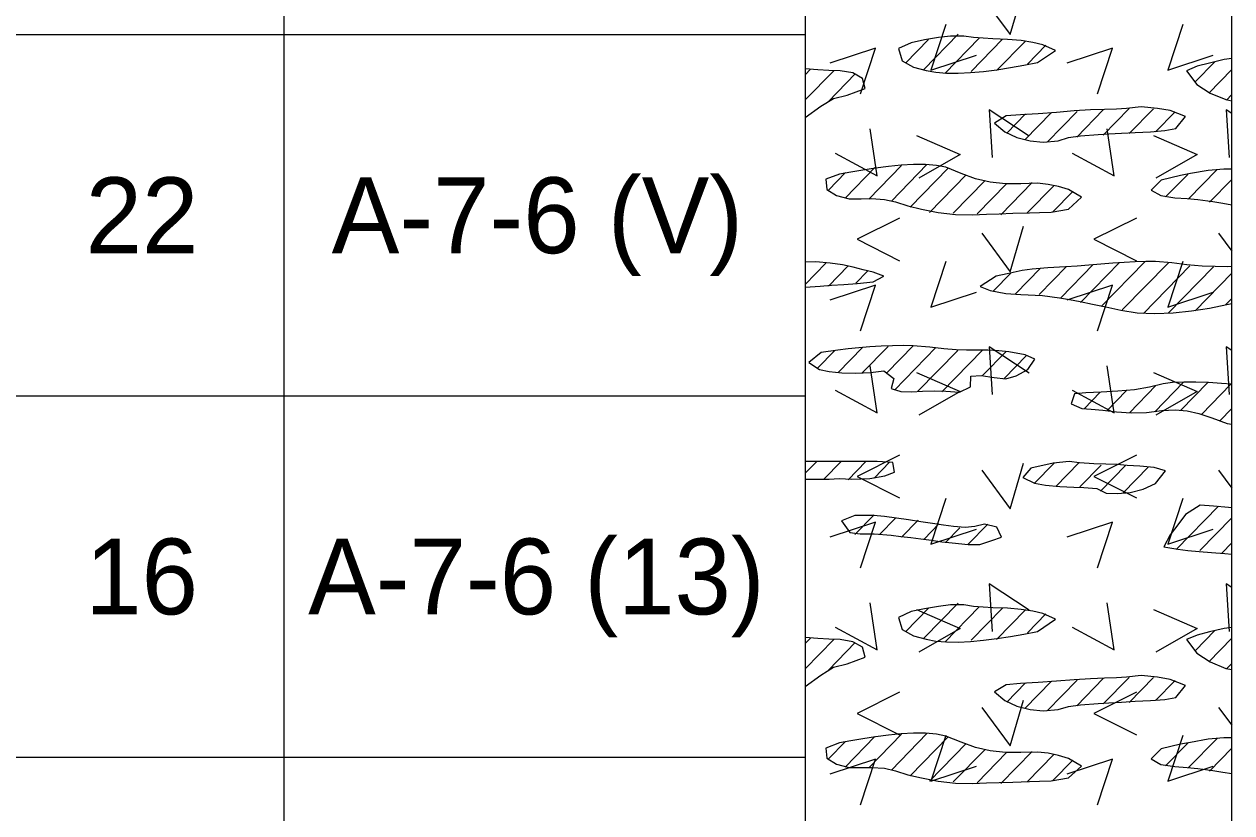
# Model space of a CAD drawing. Extents: x 0 to 0.833, y -0.323 to 0.608.
# Drawn here: x 0.7272 to 0.8333, y 0.2808 to 0.3502 of the extents above; entities that cross this region are included whole.
import ezdxf

# ---------------------------------------------------------------- set-up
doc = ezdxf.new("R2010")
doc.units = 0

msp = doc.modelspace()

# ---------------------------------------------------------------- linework, layer by layer
for points in [[(0, -0.32328), (0.83333, -0.32328), (0.83333, 0.60833), (0, 0.60833)], [(0.81233, 0.34887), (0.81063, 0.34899), (0.80977, 0.34912), (0.8086, 0.34913), (0.80755, 0.34899), (0.80632, 0.34879), (0.80513, 0.34854), (0.80403, 0.34802), (0.80436, 0.34696), (0.80536, 0.34639), (0.80647, 0.3461), (0.8073, 0.34595), (0.80824, 0.34587), (0.80926, 0.34586), (0.81035, 0.34591), (0.81149, 0.34601), (0.81267, 0.34616), (0.81386, 0.34635), (0.81506, 0.34656), (0.81625, 0.34679), (0.81783, 0.34787), (0.81673, 0.34837), (0.81585, 0.34857), (0.8148, 0.34873), (0.81361, 0.34883)], [(0.79583, 0.34196), (0.79719, 0.34295), (0.79831, 0.34365), (0.79951, 0.34392), (0.80111, 0.34453), (0.80086, 0.34541), (0.80002, 0.34589), (0.79889, 0.34608), (0.79791, 0.34611), (0.79694, 0.34617), (0.79583, 0.34625)], [(0.83265, 0.34706), (0.83136, 0.34675), (0.83028, 0.34647), (0.82934, 0.34608), (0.83026, 0.34488), (0.83142, 0.34412), (0.83279, 0.34354), (0.83333, 0.34344), (0.83333, 0.34715)], [(0.82537, 0.34291), (0.82408, 0.34276), (0.82319, 0.3427), (0.82214, 0.34267), (0.82091, 0.34264), (0.81947, 0.34254), (0.81792, 0.34242), (0.81632, 0.3423), (0.81475, 0.34221), (0.81348, 0.34211), (0.81247, 0.34147), (0.81337, 0.34071), (0.81444, 0.34021), (0.81561, 0.33992), (0.81675, 0.33981), (0.81807, 0.33993), (0.81896, 0.3402), (0.82003, 0.34035), (0.82157, 0.34047), (0.82253, 0.34053), (0.82362, 0.34058), (0.82483, 0.34064), (0.82618, 0.34071), (0.82745, 0.34082), (0.82842, 0.34099), (0.82927, 0.34205), (0.82791, 0.34257), (0.82679, 0.34277)], [(0.79885, 0.337), (0.79763, 0.33654), (0.79773, 0.33564), (0.79859, 0.33512), (0.7997, 0.33482), (0.80074, 0.33483), (0.80165, 0.33484), (0.80281, 0.33476), (0.80377, 0.33455), (0.80486, 0.3342), (0.80606, 0.33391), (0.80751, 0.33363), (0.80905, 0.33345), (0.81052, 0.33342), (0.81177, 0.33347), (0.81289, 0.33351), (0.81408, 0.33355), (0.81553, 0.33359), (0.81642, 0.33362), (0.81745, 0.33365), (0.81897, 0.33392), (0.82011, 0.33496), (0.81896, 0.33563), (0.8181, 0.33589), (0.81717, 0.33609), (0.81626, 0.33619), (0.81479, 0.33614), (0.81343, 0.33614), (0.8121, 0.33629), (0.8108, 0.33659), (0.80953, 0.33705), (0.8082, 0.3376), (0.80736, 0.33776), (0.8064, 0.33784), (0.80536, 0.33784), (0.80427, 0.33778), (0.80314, 0.33767), (0.80201, 0.33752), (0.8009, 0.33735), (0.79984, 0.33717)], [(0.83263, 0.33744), (0.83126, 0.33731), (0.82969, 0.33704), (0.82883, 0.33687), (0.82712, 0.33646), (0.82623, 0.33559), (0.82708, 0.3351), (0.82831, 0.33491), (0.82941, 0.33484), (0.83033, 0.33475), (0.83165, 0.33457), (0.83253, 0.33443), (0.83333, 0.33429), (0.83333, 0.33744)], [(0.79583, 0.32704), (0.79715, 0.32715), (0.79814, 0.32722), (0.79922, 0.3273), (0.80039, 0.32739), (0.80179, 0.32751), (0.80275, 0.32802), (0.80179, 0.32836), (0.80091, 0.32858), (0.80003, 0.3288), (0.79909, 0.32901), (0.79803, 0.32917), (0.79677, 0.32927), (0.79583, 0.32925)], [(0.82816, 0.32479), (0.82978, 0.32496), (0.83137, 0.32521), (0.8329, 0.32552), (0.83333, 0.32563), (0.83333, 0.32887), (0.83295, 0.32884), (0.83188, 0.32886), (0.83071, 0.32891), (0.82938, 0.32901), (0.82807, 0.32918), (0.82662, 0.3293), (0.82576, 0.3293), (0.82484, 0.32928), (0.82387, 0.32923), (0.82286, 0.32916), (0.82182, 0.32908), (0.82077, 0.32899), (0.81973, 0.32891), (0.81872, 0.32884), (0.81715, 0.32874), (0.81579, 0.32865), (0.81491, 0.32852), (0.81357, 0.32824), (0.8126, 0.32803), (0.81121, 0.32711), (0.8121, 0.32675), (0.81345, 0.3265), (0.81479, 0.32641), (0.81668, 0.32631), (0.81818, 0.32611), (0.81905, 0.32596), (0.82, 0.32578), (0.82107, 0.32557), (0.82225, 0.32532), (0.82357, 0.32503), (0.82501, 0.3248), (0.82656, 0.32473)], [(0.79708, 0.31981), (0.79794, 0.31963), (0.79904, 0.31952), (0.80028, 0.31949), (0.80156, 0.31954), (0.80274, 0.3197), (0.80361, 0.31903), (0.80338, 0.31814), (0.80422, 0.31787), (0.80517, 0.31785), (0.80613, 0.3179), (0.8072, 0.31793), (0.80818, 0.3179), (0.80939, 0.31783), (0.81037, 0.3183), (0.81038, 0.31924), (0.8113, 0.3193), (0.81244, 0.31912), (0.81346, 0.31901), (0.81438, 0.31927), (0.81539, 0.31981), (0.81601, 0.32072), (0.81517, 0.3211), (0.81374, 0.32137), (0.81285, 0.32146), (0.81187, 0.32152), (0.81, 0.32152), (0.8091, 0.32154), (0.808, 0.32162), (0.80678, 0.32177), (0.8053, 0.3219), (0.80443, 0.32192), (0.80349, 0.3219), (0.80251, 0.32186), (0.80152, 0.3218), (0.80054, 0.32172), (0.79959, 0.32163), (0.7987, 0.32153), (0.79722, 0.32131), (0.79614, 0.32043)], [(0.83241, 0.31859), (0.83129, 0.31866), (0.83017, 0.31869), (0.8291, 0.31869), (0.82811, 0.31866), (0.82728, 0.31857), (0.82608, 0.31827), (0.82476, 0.31804), (0.8233, 0.31791), (0.82183, 0.31782), (0.82051, 0.31776), (0.81951, 0.31767), (0.81922, 0.3168), (0.82013, 0.31638), (0.82097, 0.31633), (0.822, 0.31623), (0.82318, 0.3161), (0.82448, 0.31601), (0.82584, 0.31604), (0.82719, 0.3162), (0.82836, 0.31627), (0.8294, 0.31619), (0.83043, 0.31595), (0.83156, 0.31556), (0.83291, 0.31507), (0.83333, 0.315), (0.83333, 0.31852)], [(0.79583, 0.31018), (0.79676, 0.31017), (0.79792, 0.31019), (0.79882, 0.31023), (0.79992, 0.31018), (0.80151, 0.31023), (0.80282, 0.31048), (0.80367, 0.3108), (0.80354, 0.31164), (0.80216, 0.31173), (0.79583, 0.31173)], [(0.81822, 0.30953), (0.81944, 0.30947), (0.82033, 0.30943), (0.82145, 0.30937), (0.82229, 0.30895), (0.82324, 0.30891), (0.82438, 0.30901), (0.82555, 0.3093), (0.82662, 0.30981), (0.82749, 0.3109), (0.82651, 0.31121), (0.82524, 0.31131), (0.82413, 0.31137), (0.82324, 0.31148), (0.82226, 0.3115), (0.82121, 0.31152), (0.81995, 0.31161), (0.81902, 0.31173), (0.81761, 0.31159), (0.81566, 0.31114), (0.81496, 0.31031), (0.81598, 0.30982), (0.81695, 0.30964)], [(0.83305, 0.30768), (0.83171, 0.30779), (0.83054, 0.30789), (0.82925, 0.30707), (0.82857, 0.30616), (0.82792, 0.30527), (0.82735, 0.30424), (0.82858, 0.30402), (0.82945, 0.30392), (0.83045, 0.30382), (0.83155, 0.30373), (0.83272, 0.30363), (0.83333, 0.30358), (0.83333, 0.30767)], [(0.80066, 0.30538), (0.80188, 0.30537), (0.80339, 0.30524), (0.80423, 0.30515), (0.8051, 0.30504), (0.806, 0.30492), (0.80692, 0.3048), (0.80784, 0.30468), (0.80875, 0.30457), (0.81014, 0.30443), (0.81119, 0.30444), (0.81222, 0.30478), (0.81308, 0.30507), (0.81267, 0.30597), (0.8116, 0.30622), (0.81075, 0.30602), (0.80989, 0.30594), (0.80885, 0.30602), (0.80799, 0.30613), (0.80703, 0.30627), (0.806, 0.30644), (0.80492, 0.3066), (0.80384, 0.30676), (0.8028, 0.30689), (0.80182, 0.30698), (0.8002, 0.30699), (0.79901, 0.30652), (0.79974, 0.30548)], [(0.81233, 0.29887), (0.81063, 0.29899), (0.80977, 0.29912), (0.8086, 0.29913), (0.80755, 0.29899), (0.80632, 0.29879), (0.80513, 0.29854), (0.80403, 0.29802), (0.80436, 0.29696), (0.80536, 0.2964), (0.80647, 0.2961), (0.8073, 0.29595), (0.80824, 0.29587), (0.80926, 0.29586), (0.81035, 0.29591), (0.81149, 0.29601), (0.81267, 0.29616), (0.81386, 0.29635), (0.81506, 0.29656), (0.81625, 0.29679), (0.81783, 0.29787), (0.81673, 0.29837), (0.81585, 0.29857), (0.8148, 0.29873), (0.81361, 0.29883)], [(0.79583, 0.29196), (0.79719, 0.29295), (0.79831, 0.29365), (0.79951, 0.29393), (0.80111, 0.29453), (0.80086, 0.29541), (0.80002, 0.29589), (0.79889, 0.29608), (0.79791, 0.29611), (0.79694, 0.29617), (0.79583, 0.29625)], [(0.83265, 0.29706), (0.83136, 0.29675), (0.83028, 0.29647), (0.82934, 0.29608), (0.83026, 0.29488), (0.83142, 0.29412), (0.83279, 0.29354), (0.83333, 0.29344), (0.83333, 0.29715)], [(0.82537, 0.29291), (0.82408, 0.29276), (0.82319, 0.2927), (0.82214, 0.29267), (0.82091, 0.29264), (0.81947, 0.29254), (0.81792, 0.29242), (0.81632, 0.2923), (0.81475, 0.29221), (0.81348, 0.29211), (0.81247, 0.29147), (0.81337, 0.29071), (0.81444, 0.29021), (0.81561, 0.28992), (0.81675, 0.28981), (0.81807, 0.28993), (0.81896, 0.2902), (0.82003, 0.29035), (0.82157, 0.29047), (0.82253, 0.29053), (0.82362, 0.29058), (0.82483, 0.29065), (0.82618, 0.29071), (0.82745, 0.29082), (0.82842, 0.29099), (0.82927, 0.29205), (0.82791, 0.29257), (0.82679, 0.29277)], [(0.79885, 0.287), (0.79763, 0.28654), (0.79773, 0.28564), (0.79859, 0.28512), (0.7997, 0.28482), (0.80074, 0.28483), (0.80165, 0.28484), (0.80281, 0.28476), (0.80377, 0.28455), (0.80486, 0.2842), (0.80606, 0.28391), (0.80751, 0.28363), (0.80905, 0.28345), (0.81052, 0.28342), (0.81177, 0.28347), (0.81289, 0.28351), (0.81408, 0.28355), (0.81553, 0.28359), (0.81642, 0.28362), (0.81745, 0.28365), (0.81897, 0.28392), (0.82011, 0.28496), (0.81896, 0.28563), (0.8181, 0.28589), (0.81717, 0.28609), (0.81626, 0.28619), (0.81479, 0.28614), (0.81343, 0.28614), (0.8121, 0.28629), (0.8108, 0.28659), (0.80953, 0.28705), (0.8082, 0.2876), (0.80736, 0.28776), (0.8064, 0.28784), (0.80536, 0.28784), (0.80427, 0.28778), (0.80314, 0.28767), (0.80201, 0.28752), (0.8009, 0.28735), (0.79984, 0.28717)], [(0.83263, 0.28744), (0.83126, 0.28731), (0.82969, 0.28704), (0.82883, 0.28687), (0.82712, 0.28646), (0.82623, 0.28559), (0.82708, 0.2851), (0.82831, 0.28491), (0.82941, 0.28484), (0.83033, 0.28475), (0.83165, 0.28457), (0.83253, 0.28443), (0.83333, 0.28429), (0.83333, 0.28744)]]:
    msp.add_lwpolyline(points, close=True)
for points in [[(0.75, 0.55417), (0.75, -0.28575)], [(0.75, 0.55417), (0.75, -0.28575)], [(0.79583, 0.55417), (0.79583, -0.28575)], [(0.83333, -0.28575), (0.83333, 0.50165)], [(0.81134, 0.35262), (0.81384, 0.34925), (0.81503, 0.35325)], [(0.80818, 0.35013), (0.80687, 0.34613), (0.81087, 0.34744)], [(0.82901, 0.35013), (0.8277, 0.34613), (0.8317, 0.34744)], [(0.725, 0.34925), (0.75, 0.34925)], [(0.75, 0.34925), (0.79583, 0.34925)], [(0.80465, 0.34675), (0.80667, 0.34883)], [(0.80626, 0.34619), (0.80928, 0.34928)], [(0.80809, 0.34585), (0.81111, 0.34895)], [(0.81041, 0.34602), (0.81318, 0.34885)], [(0.81264, 0.34609), (0.81518, 0.34869)], [(0.81536, 0.34667), (0.81699, 0.34833)], [(0.80069, 0.34405), (0.802, 0.34805), (0.798, 0.34674)], [(0.82152, 0.34405), (0.82284, 0.34805), (0.81884, 0.34674)], [(0.7963, 0.34621), (0.79583, 0.34572)], [(0.8301, 0.34509), (0.83184, 0.34687)], [(0.83131, 0.34412), (0.83333, 0.34619)], [(0.79834, 0.34608), (0.79583, 0.34351)], [(0.79786, 0.34338), (0.80023, 0.34581)], [(0.83285, 0.34349), (0.83333, 0.34398)], [(0.81551, 0.34033), (0.81201, 0.34264), (0.81226, 0.33845)], [(0.81519, 0.34228), (0.81354, 0.34058)], [(0.81514, 0.34001), (0.81748, 0.34241)], [(0.81709, 0.3398), (0.81974, 0.34251)], [(0.8197, 0.34025), (0.82203, 0.34265)], [(0.82202, 0.34042), (0.8243, 0.34275)], [(0.82431, 0.34055), (0.82644, 0.34274)], [(0.82663, 0.34071), (0.82834, 0.34247)], [(0.83333, 0.34232), (0.83284, 0.34264), (0.83309, 0.33845)], [(0.79847, 0.33884), (0.80215, 0.33684), (0.80153, 0.34097)], [(0.8193, 0.33884), (0.82299, 0.33684), (0.82236, 0.34097)], [(0.80562, 0.34039), (0.80946, 0.33871), (0.80581, 0.33664)], [(0.82645, 0.34039), (0.83029, 0.33871), (0.82664, 0.33664)], [(0.80142, 0.3348), (0.8043, 0.33775)], [(0.80653, 0.33783), (0.8034, 0.33461)], [(0.79938, 0.33713), (0.79786, 0.33558)], [(0.79933, 0.33487), (0.80195, 0.33756)], [(0.80506, 0.3341), (0.8084, 0.33752)], [(0.80997, 0.33693), (0.80675, 0.33362)], [(0.82751, 0.33498), (0.82945, 0.33696)], [(0.83203, 0.33739), (0.82949, 0.33479)], [(0.81164, 0.33642), (0.80884, 0.33356)], [(0.81353, 0.33614), (0.81094, 0.33349)], [(0.81303, 0.33342), (0.81579, 0.33625)], [(0.81534, 0.33358), (0.81768, 0.33597)], [(0.83138, 0.33452), (0.83333, 0.33652)], [(0.8176, 0.33368), (0.81934, 0.33547)], [(0.83333, 0.3343), (0.83333, 0.33431)], [(0.80412, 0.33313), (0.80038, 0.33126), (0.80412, 0.32938)], [(0.81134, 0.33179), (0.81384, 0.32841), (0.81503, 0.33241)], [(0.82496, 0.33313), (0.82121, 0.33126), (0.82496, 0.32938)], [(0.83217, 0.33179), (0.83333, 0.33023)], [(0.79765, 0.32915), (0.79583, 0.32728)], [(0.80818, 0.3293), (0.80687, 0.3253), (0.81087, 0.32661)], [(0.82004, 0.32571), (0.82346, 0.32922)], [(0.82569, 0.32929), (0.82184, 0.32535)], [(0.82775, 0.32919), (0.8237, 0.32505)], [(0.82901, 0.3293), (0.8277, 0.3253), (0.8317, 0.32661)], [(0.7996, 0.32894), (0.79786, 0.32715)], [(0.8013, 0.32846), (0.80027, 0.32741)], [(0.81392, 0.3283), (0.81235, 0.32669)], [(0.8143, 0.32648), (0.8165, 0.32873)], [(0.8164, 0.32641), (0.81879, 0.32886)], [(0.81829, 0.32613), (0.82114, 0.32905)], [(0.82964, 0.32892), (0.82557, 0.32474)], [(0.83173, 0.32885), (0.82774, 0.32476)], [(0.83333, 0.32827), (0.83012, 0.32498)], [(0.80069, 0.32322), (0.802, 0.32722), (0.798, 0.32591)], [(0.82152, 0.32322), (0.82284, 0.32722), (0.81884, 0.32591)], [(0.83281, 0.32552), (0.83333, 0.32606)], [(0.79871, 0.31955), (0.80085, 0.32174)], [(0.80083, 0.31951), (0.80311, 0.32185)], [(0.80534, 0.32192), (0.80299, 0.31951)], [(0.80367, 0.318), (0.80732, 0.32174)], [(0.81551, 0.31949), (0.81201, 0.32181), (0.81226, 0.31762)], [(0.83333, 0.32148), (0.83284, 0.32181), (0.83309, 0.31762)], [(0.79844, 0.32149), (0.79691, 0.31992)], [(0.80571, 0.31788), (0.80924, 0.32149)], [(0.81142, 0.32151), (0.80785, 0.31786)], [(0.81141, 0.31929), (0.81348, 0.32141)], [(0.81528, 0.32104), (0.81331, 0.31903)], [(0.79847, 0.31801), (0.80215, 0.31601), (0.80153, 0.32014)], [(0.8193, 0.31801), (0.82299, 0.31601), (0.82236, 0.32014)], [(0.80562, 0.31956), (0.80946, 0.31787), (0.80581, 0.31581)], [(0.82645, 0.31956), (0.83029, 0.31787), (0.82664, 0.31581)], [(0.82909, 0.31869), (0.82656, 0.3161)], [(0.82885, 0.31623), (0.83122, 0.31866)], [(0.83325, 0.31852), (0.83065, 0.31586)], [(0.725, 0.3175), (0.75, 0.3175)], [(0.75, 0.3175), (0.79583, 0.3175)], [(0.82035, 0.31637), (0.82176, 0.31782)], [(0.82233, 0.31619), (0.82408, 0.31798)], [(0.82433, 0.31602), (0.82666, 0.31841)], [(0.83333, 0.3164), (0.83227, 0.31531)], [(0.80412, 0.3123), (0.80038, 0.31042), (0.80412, 0.30855)], [(0.82496, 0.3123), (0.82121, 0.31042), (0.82496, 0.30855)], [(0.79583, 0.3107), (0.79681, 0.3117)], [(0.79898, 0.31172), (0.79747, 0.31017)], [(0.80116, 0.31173), (0.79959, 0.31013)], [(0.80328, 0.31169), (0.80188, 0.31026)], [(0.81134, 0.31096), (0.81384, 0.30758), (0.81503, 0.31158)], [(0.8177, 0.31159), (0.81596, 0.30981)], [(0.81988, 0.31161), (0.81785, 0.30953)], [(0.82185, 0.31142), (0.81997, 0.30949)], [(0.824, 0.31141), (0.82178, 0.30913)], [(0.82601, 0.31125), (0.82378, 0.30897)], [(0.83217, 0.31096), (0.83333, 0.30939)], [(0.80818, 0.30847), (0.80687, 0.30447), (0.81087, 0.30578)], [(0.82901, 0.30847), (0.8277, 0.30447), (0.8317, 0.30578)], [(0.80188, 0.30703), (0.8002, 0.30531)], [(0.83217, 0.30781), (0.82844, 0.30399)], [(0.80069, 0.30239), (0.802, 0.30639), (0.798, 0.30507)], [(0.8038, 0.30679), (0.80237, 0.30532)], [(0.80575, 0.30657), (0.80429, 0.30508)], [(0.80758, 0.30624), (0.80627, 0.30489)], [(0.80941, 0.3059), (0.80816, 0.30462)], [(0.81188, 0.30621), (0.81016, 0.30446)], [(0.82152, 0.30239), (0.82284, 0.30639), (0.81884, 0.30507)], [(0.83333, 0.30679), (0.83052, 0.30391)], [(0.83333, 0.30457), (0.83245, 0.30367)], [(0.81551, 0.29866), (0.81201, 0.30097), (0.81226, 0.29678)], [(0.83333, 0.30065), (0.83284, 0.30097), (0.83309, 0.29678)], [(0.79847, 0.29718), (0.80215, 0.29518), (0.80153, 0.2993)], [(0.80465, 0.29675), (0.80667, 0.29883)], [(0.80562, 0.29872), (0.80946, 0.29704), (0.80581, 0.29498)], [(0.80626, 0.29619), (0.80928, 0.29928)], [(0.80809, 0.29585), (0.81111, 0.29895)], [(0.81041, 0.29602), (0.81318, 0.29885)], [(0.81264, 0.29609), (0.81518, 0.29869)], [(0.81536, 0.29667), (0.81699, 0.29833)], [(0.8193, 0.29718), (0.82299, 0.29518), (0.82236, 0.2993)], [(0.82645, 0.29872), (0.83029, 0.29704), (0.82664, 0.29498)], [(0.7963, 0.29621), (0.79583, 0.29572)], [(0.8301, 0.29509), (0.83184, 0.29688)], [(0.79834, 0.29608), (0.79583, 0.29351)], [(0.79786, 0.29338), (0.80023, 0.29581)], [(0.83131, 0.29412), (0.83333, 0.29619)], [(0.83285, 0.29349), (0.83333, 0.29398)], [(0.81519, 0.29228), (0.81354, 0.29058)], [(0.81514, 0.29001), (0.81748, 0.29241)], [(0.81709, 0.2898), (0.81974, 0.29251)], [(0.8197, 0.29025), (0.82203, 0.29265)], [(0.82202, 0.29042), (0.8243, 0.29275)], [(0.82431, 0.29055), (0.82644, 0.29274)], [(0.82663, 0.29071), (0.82834, 0.29247)], [(0.80412, 0.29146), (0.80038, 0.28959), (0.80412, 0.28771)], [(0.82496, 0.29146), (0.82121, 0.28959), (0.82496, 0.28771)], [(0.81134, 0.29012), (0.81384, 0.28675), (0.81503, 0.29075)], [(0.83217, 0.29012), (0.83333, 0.28856)], [(0.80142, 0.2848), (0.8043, 0.28775)], [(0.80653, 0.28783), (0.8034, 0.28461)], [(0.79938, 0.28713), (0.79786, 0.28558)], [(0.79933, 0.28487), (0.80195, 0.28756)], [(0.80506, 0.2841), (0.8084, 0.28752)], [(0.80997, 0.28693), (0.80675, 0.28362)], [(0.80818, 0.28763), (0.80687, 0.28363), (0.81087, 0.28495)], [(0.82751, 0.28498), (0.82945, 0.28696)], [(0.82901, 0.28763), (0.8277, 0.28363), (0.8317, 0.28495)], [(0.83203, 0.28739), (0.82949, 0.28479)], [(0.725, 0.28575), (0.75, 0.28575)], [(0.75, 0.28575), (0.79583, 0.28575)], [(0.81164, 0.28642), (0.80884, 0.28356)], [(0.81353, 0.28614), (0.81094, 0.28349)], [(0.81303, 0.28342), (0.81579, 0.28625)], [(0.81534, 0.28358), (0.81768, 0.28597)], [(0.83138, 0.28452), (0.83333, 0.28652)], [(0.80069, 0.28155), (0.802, 0.28555), (0.798, 0.28424)], [(0.8176, 0.28368), (0.81934, 0.28547)], [(0.82152, 0.28155), (0.82284, 0.28555), (0.81884, 0.28424)], [(0.83333, 0.2843), (0.83333, 0.28431)]]:
    msp.add_lwpolyline(points)

# ---------------------------------------------------------------- texts
for s, p in [('22', (0.73257, 0.33004)), ('A-7-6 (V)', (0.7542, 0.33004)), ('16', (0.73253, 0.29829)), ('A-7-6 (13)', (0.75213, 0.29829))]:
    msp.add_text(s, height=0.006667).set_placement(p)

doc.saveas('drawing.dxf')
